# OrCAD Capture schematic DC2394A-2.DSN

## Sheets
1 PAGE1: size Custom
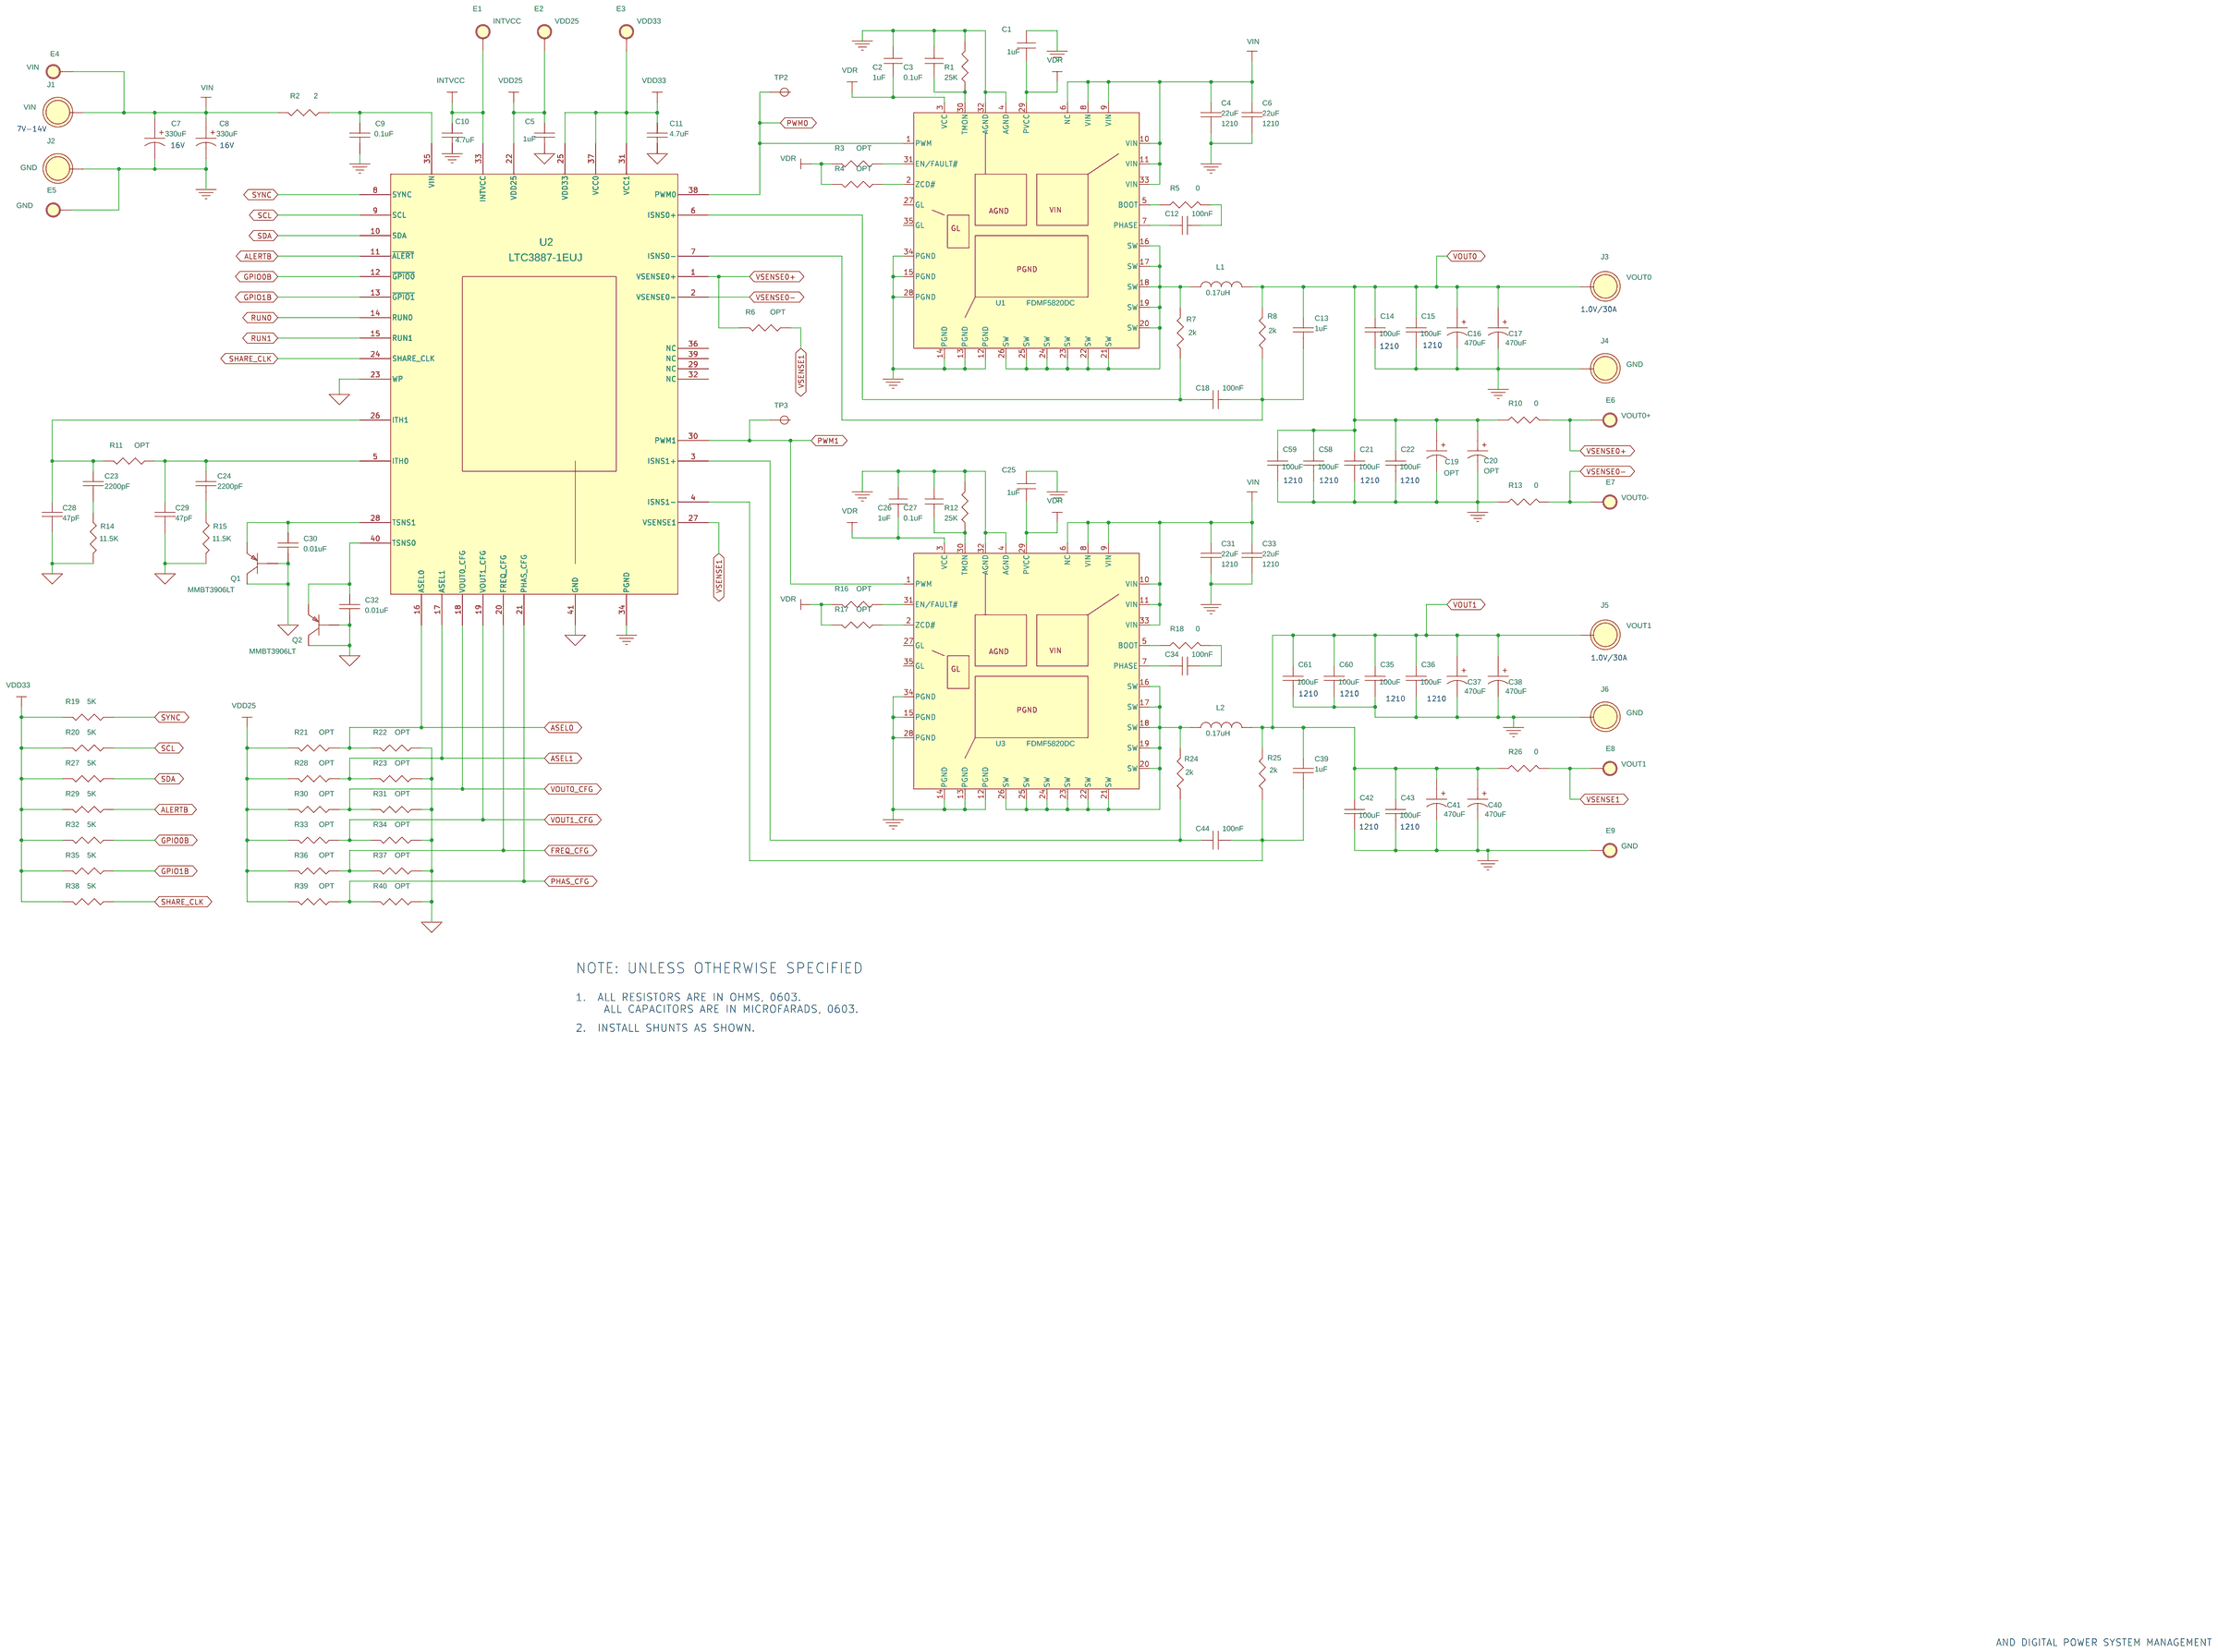
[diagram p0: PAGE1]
2 PAGE2: size Custom; title: HIGH DENSITY  DC/DC CONVERTER WITH POWER SYSTEM MANAGEMENT; rev: 1; company: TM
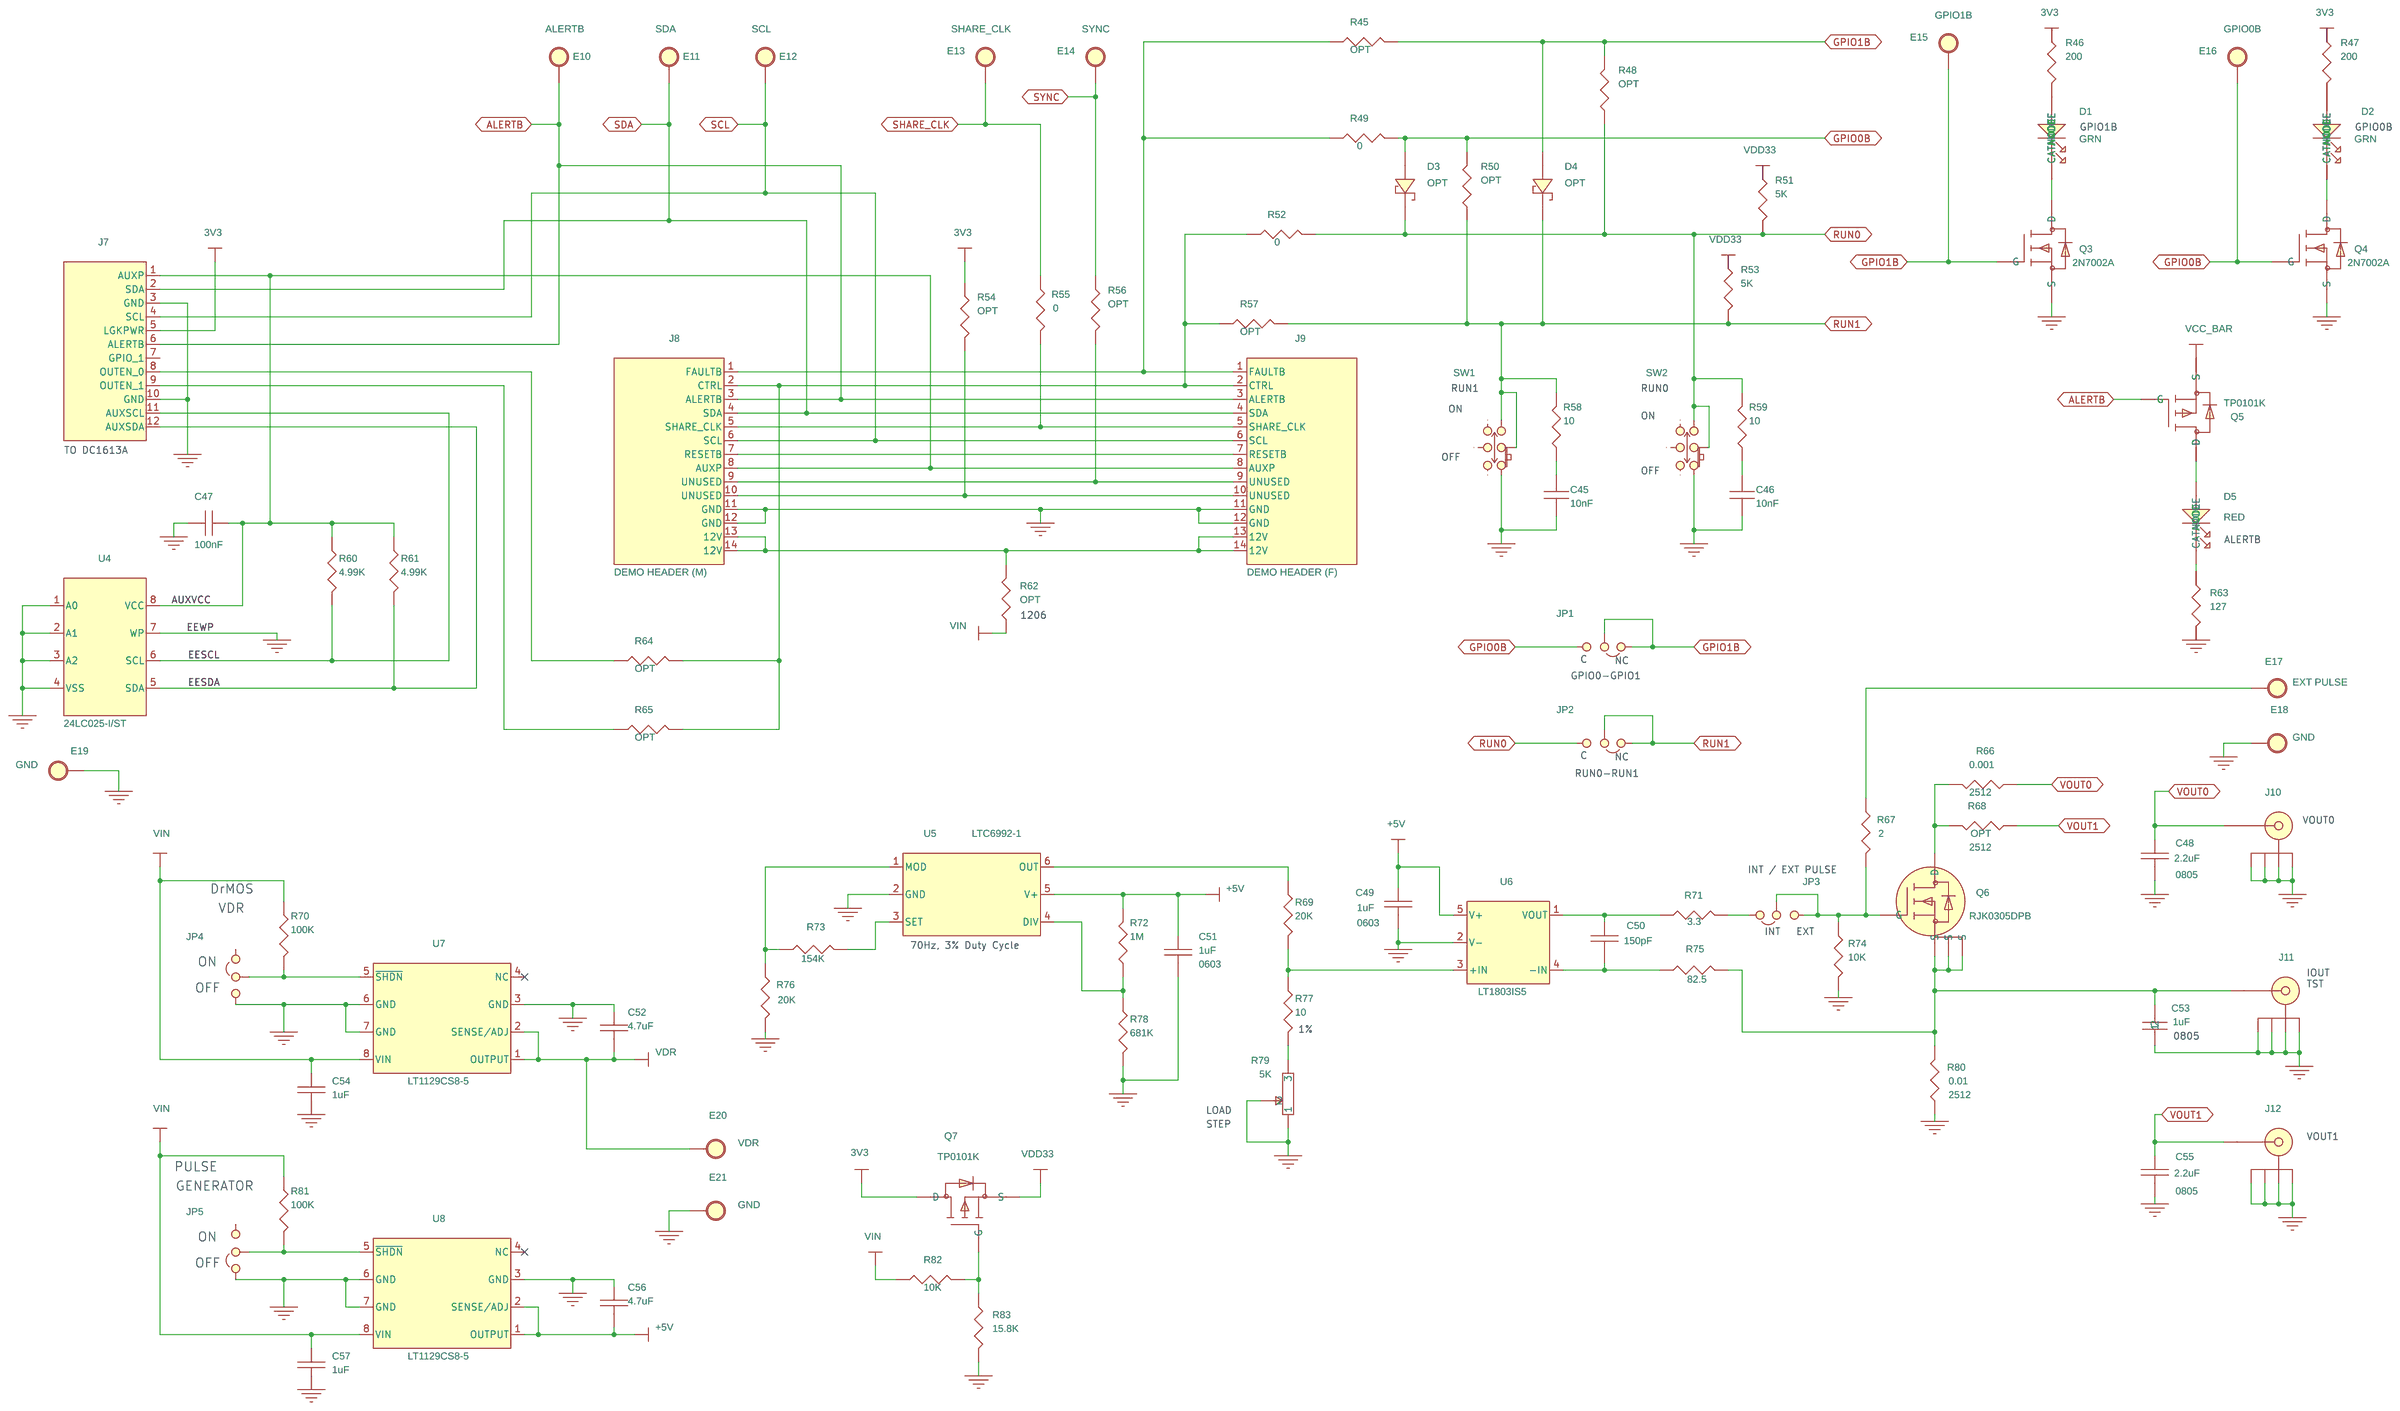
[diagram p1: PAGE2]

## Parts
sheet PAGE1
C1  1uF  [0402]
C2  1uF  [0402]
C3  0.1uF  [0402]
C4  22uF  [1210]
C5  1uF  [0603]
C6  22uF  [1210]
C7  330uF  [CAP_SANYO_F12]
C8  330uF  [CAP_SANYO_F12]
C9  0.1uF  [0603]
C10  4.7uF  [0603]
C11  4.7uF  [0603]
C12  100nF  [0402]
C13  1uF  [0603]
C14  100uF  [1210]
C15  100uF  [1210]
C16  470uF  [SANYO-C3-D2E(TPE)]
C17  470uF  [SANYO-C3-D2E(TPE)]
C18  100nF  [0603]
C19  OPT  [SANYO-C3-D2E(TPE)]
C20  OPT  [SANYO-C3-D2E(TPE)]
C21  100uF  [1210]
C22  100uF  [1210]
C23  2200pF  [0603]
C24  2200pF  [0603]
C25  1uF  [0402]
C26  1uF  [0402]
C27  0.1uF  [0402]
C28  47pF  [0603]
C29  47pF  [0603]
C30  0.01uF  [0603]
C31  22uF  [1210]
C32  0.01uF  [0603]
C33  22uF  [1210]
C34  100nF  [0402]
C35  100uF  [1210]
C36  100uF  [1210]
C37  470uF  [SANYO-C3-D2E(TPE)]
C38  470uF  [SANYO-C3-D2E(TPE)]
C39  1uF  [0603]
C40  470uF  [SANYO-C3-D2E(TPE)]
C41  470uF  [SANYO-C3-D2E(TPE)]
C42  100uF  [1210]
C43  100uF  [1210]
C44  100nF  [0603]
C58  100uF  [1210]
C59  100uF  [1210]
C60  100uF  [1210]
C61  100uF  [1210]
E1  TURRETS  [TURRETS]
E2  TURRETS  [TURRETS]
E3  TURRETS  [TURRETS]
E4  TURRETS  [TURRETS]
E5  GND  [TURRETS]
E6  TURRETS  [TURRETS]
E7  TURRETS  [TURRETS]
E8  TURRETS  [TURRETS]
E9  TURRETS  [TURRETS]
J1  VIN  [KEY-575-4]
J2  GND  [KEY-575-4]
J3  VOUT0  [CON\LUG\10]
J4  GND  [CON\LUG\10]
J5  VOUT1  [CON\LUG\10]
J6  GND  [CON\LUG\10]
L1  0.17uH  [PA0515]
L2  0.17uH  [PA0515]
Q1  MMBT3906LT  [SOT-416]
Q2  MMBT3906LT  [SOT-416]
R1  25K  [0402]
R2  2  [0603]
R3  OPT  [0402]
R4  OPT  [0402]
R5  0  [0402]
R6  OPT  [0603]
R7  2k  [0603]
R8  2k  [0603]
R10  0  [0603]
R11  OPT  [0603]
R12  25K  [0402]
R13  0  [0603]
R14  11.5K  [0603]
R15  11.5K  [0603]
R16  OPT  [0402]
R17  OPT  [0402]
R18  0  [0402]
R19  5K  [0603]
R20  5K  [0603]
R21  OPT  [0603]
R22  OPT  [0603]
R23  OPT  [0603]
R24  2k  [0603]
R25  2k  [0603]
R26  0  [0603]
R27  5K  [0603]
R28  OPT  [0603]
R29  5K  [0603]
R30  OPT  [0603]
R31  OPT  [0603]
R32  5K  [0603]
R33  OPT  [0603]
R34  OPT  [0603]
R35  5K  [0603]
R36  OPT  [0603]
R37  OPT  [0603]
R38  5K  [0603]
R39  OPT  [0603]
R40  OPT  [0603]
TP2  TURRETS  [PAD]
TP3  TURRETS  [PAD]
U1  DC/DC Converters  [FDMF5821DC]
U2  LTC3887-1EUJ  [UJ-40-QFN(6X6mm)]
U3  DC/DC Converters  [FDMF5821DC]
sheet PAGE2
C45  10nF  [0603]
C46  10nF  [0603]
C47  100nF  [0603]
C48  2.2uF  [0805]
C49  1uF  [0603]
C50  150pF  [0603]
C51  1uF  [0603]
C52  4.7uF  [1206]
C53  1uF  [0805]
C54  1uF  [1206]
C55  2.2uF  [0805]
C56  4.7uF  [0603]
C57  1uF  [1206]
D1  LED  [WURTH_LED]
D2  LED  [WURTH_LED]
D3  OPT  [SOD323]
D4  OPT  [SOD323]
D5  LED  [WURTH_LED]
E10  TURRETS  [TURRETS]
E11  TURRETS  [TURRETS]
E12  TURRETS  [TURRETS]
E13  TURRETS  [TURRETS]
E14  TURRETS  [TURRETS]
E15  TURRETS  [TURRETS]
E16  TURRETS  [TURRETS]
E17  TURRETS  [TURRETS]
E18  TURRETS  [TURRETS]
E19  TURRETS  [TURRETS]
E20  TURRETS  [TURRETS]
E21  TURRETS  [TURRETS]
J7  HD2X6-079  [HD2X6-079-MOLEX]
J8  DEMO HEADER (M)  [NPPN072FJFN]
J9  DEMO HEADER (F)  [NPPN072FJFN-RC]
J10  CONNEX 112404  [BNC]
J11  CONNEX 112404  [BNC]
J12  CONNEX 112404  [BNC]
JP1  JP3X1/079\NO\12  [HD1X3-079]
JP2  JP3X1/079\NO\12  [HD1X3-079]
JP3  JP3X1/079\NO\12  [HD1X3-079]
JP4  JP3X1/079\NO\12  [HD1X3-079]
JP5  JP3X1/079\NO\12  [HD1X3-079]
Q3  2N7002A  [SOT-23]
Q4  2N7002A  [SOT-23]
Q5  TP0101K  [SOT-23]
Q6  RJK0305DPB  [LFPAK]
Q7  TP0101K  [SOT-23]
R45  OPT  [0603]
R46  200  [0603]
R47  200  [0603]
R48  OPT  [0603]
R49  0  [0603]
R50  OPT  [0603]
R51  5K  [0603]
R52  0  [0603]
R53  5K  [0603]
R54  OPT  [0603]
R55  0  [0603]
R56  OPT  [0603]
R57  OPT  [0603]
R58  10  [0603]
R59  10  [0603]
R60  4.99K  [0603]
R61  4.99K  [0603]
R62  OPT  [0603]
R63  127  [0603]
R64  OPT  [0603]
R65  OPT  [0603]
R66  0.001  [2512]
R67  2  [0603]
R68  OPT  [2512]
R69  20K  [0603]
R70  100K  [0603]
R71  3.3  [0603]
R72  1M  [0603]
R73  154K  [0603]
R74  10K  [0603]
R75  82.5  [0603]
R76  20K  [0603]
R77  10  [0603]
R78  681K  [0603]
R79  5K  [POTENTIOMETER/3386]
R80  0.01  [2512]
R81  100K  [0603]
R82  10K  [0603]
R83  15.8K  [0603]
SW1  JP3X1/079\NO\12  [JS202011]
SW2  JP3X1/079\NO\12  [JS202011]
U4  24LC025-I/ST  [TSSOP-8_4.4MM]
U5  LTC6992-1  [S6-TSOT23]
U6  LT1803IS5  [S5-TSOT23]
U7  LT1129CS8-5  [SO8NB]
U8  LT1129CS8-5  [SO8NB]

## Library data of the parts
C1 C25 = CAP-NP: CAP, 0603 2.2uF 10% 16V X5R; Grade: X5R; Voltage rating: 16V
C2 C3 C26 C27 = CAP-NP: CAP, 0603 2.2uF 10% 16V X5R; Grade: X5R; Part Number: C0603C225K4PAC; Voltage rating: 16V
C4 C6 C31 C33 = CAP1210_2: Component: cap; Manufacturer: Taiyo Yuden; Manufacturer P/N: GMK325BJ106KN-T; Tolerance: 10%; Type: cer 1210; Vendor: Digikey; Vendor P/N: 587-1439-1-ND; Volts/Amps/Watts: 35V
C5 C10 = CAP_3: CAP, 0402 1uF 20% 10V X5R; Manufacturer: Taiyo Yuden; Manufacturer P/N: EMK107B7105KA-T; Part Number: TDK C1005X5R1A105M; Type: cer 0603 X7R; Vendor: Digikey; Vendor P/N: 587-1241-1-ND; Volts/Amps/Watts: 10V
C7 C8 = CAPR12X5_0: Component: cap; Manufacturer: SANYO; Manufacturer P/N: 16SVP330M; Tolerance: 20%; Type: OS-CON; Volts/Amps/Watts: 16V
C9 = CAP_3: CAP, 0402 0.1uF 10% 16V X7R; Manufacturer: TDK; Manufacturer P/N: C1608X7R1H104K; Part Number: AVX 0402YC103KAT2A; Part Type: 0402; Tolerance: 10%; Type: cer 0603 X7R; Vendor: Digikey; Vendor P/N: 445-1314-1-ND; Volts/Amps/Watts: 16V
C11 = CAP_3: CAP, 0402 1uF 20% 10V X5R; Manufacturer: Taiyo Yuden; Manufacturer P/N: EMK107B7105KA-T; Part Number: TDK C1005X5R1A105M; Part Type: 0402; Type: cer 0603 X7R; Vendor: Digikey; Vendor P/N: 587-1241-1-ND; Volts/Amps/Watts: 10V
C12 C18 C34 C44 = EMK107BJ224MA: CAP, 0603 0.22uF 10% 25V X5R
C13 C39 = CAP_3: CAP, 0805 47uF 20% 6.3V X5R; Component: cap; Manufacturer: TDK; Manufacturer P/N: C3225X5R0J107M; Part Number: TAIYO YUDEN JMK212BJ476MG-T; Part Type: CAP1210; Tolerance: 20%; Type: cer 1210 X5R; Vendor: Digikey; Vendor P/N: 445-1437-1-ND; Volts/Amps/Watts: 6.3v
C14 C15 C21 C22 C58-C61 = CAP_3: Component: cap; Manufacturer: TDK; Manufacturer P/N: C3225X5R0J107M; Part Type: CAP1210; Tolerance: 20%; Type: cer 1210 X5R; Vendor: Digikey; Vendor P/N: 445-1437-1-ND; Volts/Amps/Watts: 6.3v
C16 C17 C19 C20 C37 C38 C40 C41 = CAPR12X5_0: Component: cap; Manufacturer: SANYO; Manufacturer P/N: 6TPF330M9L; Tolerance: 20%; Type: TANT; Volts/Amps/Watts: 6.3V
C23 C24 = CAP_3: CAP, 0402 1000pF 10% 25V X7R; Component: cap; Manufacturer: TDK; Manufacturer P/N: C1608C0G1H102J; Part Number: AVX 04023C102KAT2A; Tolerance: 5%; Type: cer 0603; Vendor: Digikey; Vendor P/N: 445-1293-1-ND; Volts/Amps/Watts: 50V
C28 C29 = CAP_3: CAP, 0402 47pF 10% 50V NPO; Component: cap; Manufacturer: TDK; Manufacturer P/N: C1608C0G1H101J; Part Number: AVX 04025A470KAT; Tolerance: 5%; Type: cer 0603; Vendor: Digikey; Vendor P/N: 445-1281-1-ND
C30 C32 = CAP0603_1: CAP, 0402 0.1uF 10% 16V X7R; Component: cap; Manufacturer: TDK; Manufacturer P/N: C1608X7R1H103K; Part Number: AVX 0402YC103KAT2A; Part Type: 0402; Tolerance: 10%; Type: cer 0603; Vendor: Digikey; Vendor P/N: 445-1311-1-ND; Volts/Amps/Watts: 50V
C35 C36 C42 C43 = CAP_3: Component: cap; Manufacturer: TDK; Manufacturer P/N: C3225X5R0J107M; Tolerance: 20%; Type: cer 1210 X5R; Vendor: Digikey; Vendor P/N: 445-1437-1-ND; Volts/Amps/Watts: 6.3v
E1 = TURRETS_2: Label: INTVCC; Vendor: Digikey; Vendor P/N: 1593-2K-ND
E2 = TURRETS_2: Label: VDD25; Vendor: Digikey; Vendor P/N: 1593-2K-ND
E3 = TURRETS_2: Label: VDD33; Vendor: Digikey; Vendor P/N: 1593-2K-ND
E4 = TURRETS_2: Label: VIN; Manufacturer: Keystone; Manufacturer P/N: 1593-2; Vendor: Digikey; Vendor P/N: 1593-2K-ND
E5 = TURRETS_2: Manufacturer: Keystone; Manufacturer P/N: 1593-2; Vendor: Digikey; Vendor P/N: 1593-2K-ND
E6 = TURRETS_2: Label: VOUT0+; Vendor: Digikey; Vendor P/N: 1593-2K-ND
E7 = TURRETS_2: Label: VOUT0-; Vendor: Digikey; Vendor P/N: 1593-2K-ND
E8 = TURRETS_2: Label: VOUT1; Vendor: Digikey; Vendor P/N: 1593-2K-ND
E9 = TURRETS_2: Label: GND; Vendor: Digikey; Vendor P/N: 1593-2K-ND
J1 = E_4: STATUS: 1.6V, 1.8V, 2.0V OR 2.5V @ 15A
J2 J4 J6 = E_4: STATUS: 1.6V, 1.8V, 2.0V OR 2.5V @ 15A; VALUE2: J1
J3 J5 = E_4: VALUE2: 1V@80A
L1 L2 = 744355147_Wurth: 4th Part Field: WURTH EL.; 5th Part Field: DELTA
Q1 Q2 = MMBT3906LT1_0: XSTR, PNP SMALL SIGNAL; Component: trans; Manufacturer P/N: MMBT3906LT1G; Part Number: ON SEMI MMBT3906TTI; Part Type: MMBT3906LT1; Vendor P/N: MMBT3906LT1GOSCT-ND
R1 R12 = CJ06-000M: RES, 0603 0 OHM JUMPER
R2 = RES0603_9: RES, 0402 2 OHMS 1% 1/16W; Manufacturer: Panasonic; Part Number: VISHAY CRCW04022R00FNEA; Part Type: 0402; Vendor: Digikey; Vendor P/N: P100HCT-ND; Volts/Amps/Watts: 0.1W
R3 R4 R16 R17 = RES0603_9: Manufacturer: Panasonic; Manufacturer P/N: ERJ-3EKF2002V; Vendor: Digikey; Vendor P/N: P20.0KHCT-ND; Volts/Amps/Watts: 0.1W
R5 R7 R8 R10 R13 R18 R24-R26 = CJ06-000M: RES, 0603 0 OHM JUMPER; Part Number: YAGEO RC0603FR-070RL
R6 R11 = RES0603_9: RES, 0402 0 OHM JUMPER; Manufacturer: Panasonic; Manufacturer P/N: ERJ-3EKF2002V; Part Number: VISHAY CRCW04020000Z0EA; Vendor: Digikey; Vendor P/N: P20.0KHCT-ND; Volts/Amps/Watts: 0.1W
R14 R15 = RES0603_9: RES, 0402 4.53k OHMS 1% 1/16W; Component: res; Label: <label>; Manufacturer: Panasonic; Manufacturer P/N: ERJ-3EKF5901V; Part Number: VISHAY CRCW04024K53FKED; Tolerance: 1%; Vendor: Digikey; Vendor P/N: P5.90KHCT-ND; Volts/Amps/Watts: 0.1W
R19 R20 R27 R29 R32 R35 R38 = RES0603_9: RES, 0402 5k OHMS 5% 1/16W; Manufacturer: Panasonic; Manufacturer P/N: ERJ-3EKF2002V; Part Number: VISHAY CRCW04025K00JNED; Vendor: Digikey; Vendor P/N: P20.0KHCT-ND; Volts/Amps/Watts: 0.1W
R21-R23 R28 R30 R31 R33 R34 R36 R37 R39 R40 = RES0603_9: RES, 0603 OPTION; Manufacturer: Panasonic; Manufacturer P/N: ERJ-3EKF2002V; Part Number: OPTION; Vendor: Digikey; Vendor P/N: P20.0KHCT-ND; Volts/Amps/Watts: 0.1W
TP2 TP3 = PAD_2: Component: tp; Label: <Label>; Vendor: Digikey; Vendor P/N: 1593-2K-ND
U1 U3 = R2J20602NP(Renesas)_5: 5th Part Field: FDMF5820DC
U2 = LTC3880-M0001_15: IC,; Component: IC; Manufacturer: LTC; Manufacturer P/N: LTC3880_M0001; Part Number: LINEAR TECH LTC3880EUJ; Part Type: LTC3880EUF; Vendor: LTC; Vendor P/N: LTC3880_M0001
C45 C46 = CAP_NP: CAP, 0603 10nF 10% 25V X7R; Part Number: AVX 06033C103KAT2A
C47 = CAP_NP: CAP, 0603 100nF 20% 16V X7R; Part Number: AVX 0603YC104MAT2A
C48 C55 = CAP1206_1: Manufacturer: Kemet; Manufacturer P/N: C1206C106K8RACTU; Tolerance: 10%; Type: cer 1206 X7R; Vendor: Digikey; Vendor P/N: 399-4937-1-ND; Volts/Amps/Watts: 10V
C49 C51 C54 C57 = CAP1206_1: Manufacturer: AVX; Manufacturer P/N: 12063C105KAT2A; Tolerance: 10%; Type: cer 1206 X7R; Vendor: Digikey; Vendor P/N: 478-1567-1-ND; Volts/Amps/Watts: 25V
C50 = CAP0603_2: Component: cap; Manufacturer: TDK; Manufacturer P/N: C1608C0G1H102J; Tolerance: 5%; Type: cer 0603; Vendor: Digikey
C52 C56 = CAP1206_1: Manufacturer: AVX; Tolerance: 10%; Type: cer 1206 X7R; Vendor: Digikey; Vendor P/N: 478-1567-1-ND; Volts/Amps/Watts: 25V
C53 = CAP_NP_1: CAP, 0603 1.5nF 10% 50V X7R; Part Number: AVX 06033C152KAT
D1 D2 = LED_1: 1%: GRN
D3 D4 = DIODE_SCHOTTKY_9: DIODE, SCHOTTKY 30V, 100mA; Part Number: CENTRAL SEMI CMDSH-3-TR
D5 = LED_1: 1%: RED
E10 = TURRETS_2: Label: ALERTB; Manufacturer: Keystone; Manufacturer P/N: 1593-2; Vendor: Digikey; Vendor P/N: 1593-2K-ND
E11 = TURRETS_2: Label: SDA; Manufacturer: Keystone; Manufacturer P/N: 1593-2; Vendor: Digikey; Vendor P/N: 1593-2K-ND
E12 = TURRETS_2: Label: SCL; Manufacturer: Keystone; Manufacturer P/N: 1593-2; Vendor: Digikey; Vendor P/N: 1593-2K-ND
E13 = TURRETS_2: Label: SHARE_CLK; Manufacturer: Keystone; Manufacturer P/N: 1593-2; Vendor: Digikey; Vendor P/N: 1593-2K-ND
E14 = TURRETS_2: Label: SYNC; Manufacturer: Keystone; Manufacturer P/N: 1593-2; Vendor: Digikey; Vendor P/N: 1593-2K-ND
E15 = TURRETS_2: Label: GPIO1B; Manufacturer: Keystone; Manufacturer P/N: 1593-2; Vendor: Digikey; Vendor P/N: 1593-2K-ND
E16 = TURRETS_2: Label: GPIO0B; Manufacturer: Keystone; Manufacturer P/N: 1593-2; Vendor: Digikey; Vendor P/N: 1593-2K-ND
E17 = TURRETS_2: Label: EXT PULSE; Manufacturer: Keystone; Manufacturer P/N: 1593-2; Vendor: Digikey; Vendor P/N: 1593-2K-ND
E18 E19 E21 = TURRETS_2: Label: GND; Manufacturer: Keystone; Manufacturer P/N: 1593-2; Vendor: Digikey; Vendor P/N: 1593-2K-ND
E20 = TURRETS_2: Label: VDR; Manufacturer: Keystone; Manufacturer P/N: 1593-2; Vendor: Digikey; Vendor P/N: 1593-2K-ND
J7 = HD2X6-079-PMBUS_2: HEADER, 12PIN 2mm STR DL; Label: DC1427A HEADER; Manufacturer: MOLEX; Manufacturer P/N: 87831-1220; Part Number: FCI 98414-G06-12ULF; Type: header 12POS 2MM VERT; Vendor: Digikey; Vendor P/N: WM18561-ND
J8 = PMBUS_HEADER20_3: HEADER, 20PIN DUAL ROW R/A; Component: con; Manufacturer: Mill Max; Manufacturer P/N: 802-40-020-20-0001; Part Number: MILL MAX 802-40-020-20-0001; Part Type: HDR_2X10_RA_REV; Type: header RA 20 dual row; Vendor: LTC; Vendor P/N: 802-40-020-20-001
J9 = PMBUS_CONNECTOR20_3: CONN, SOCKET 20PIN  DUAL ROW R/A; Component: con; Manufacturer: Mill Max; Manufacturer P/N: 803-93-020-20-001; Part Number: MILL MAX 803-93-020-20-001; Part Type: HDR2X10RA; Type: conn  RA 20 dual row; Vendor: LTC; Vendor P/N: 803-93-020-20-001
J10-J12 = BNC5-SCH_0: CONN,BNC,5 PINS
JP1-JP3 JP5 = JP3X1_079_NO_12_2
JP4 = JP3X1_079_NO_12_1
Q3 Q4 = TRANSISTOR_0: XSTR, N-CHANNEL DMOS FET
Q5 Q7 = P-MOSFET: XSTR, N-CHANNEL DMOS FET
Q6 = MOS_FET_5: XSTR, N-CHANNEL DMOS FET
R45 R49 R52 R57 = RES0603_0: RES, 0603 0 OHMS JUMPER; Label: OPT 0; Manufacturer: Rohm; Manufacturer P/N: RHM0.0GCT-ND; Part Number: VISHAY CRCW06030000Z0EA; Tolerance: 5%; Vendor: Digikey; Vendor P/N: RHM0.0GCT-ND; Volts/Amps/Watts: 0.1W
R46 R47 R63 = RES0603_9: Label: OPT 0; Manufacturer: Rohm; Manufacturer P/N: RHM0.0GCT-ND; Tolerance: 5%; Vendor: Digikey; Vendor P/N: RHM0.0GCT-ND; Volts/Amps/Watts: 0.1W
R48 R50 R51 R53 R54 R56 R65 = RES0603_0: RES, 0603 OPTION; Label: OPT 0; Manufacturer: Rohm; Manufacturer P/N: RHM0.0GCT-ND; Part Number: OPTION; Tolerance: 5%; Vendor: Digikey; Vendor P/N: RHM0.0GCT-ND; Volts/Amps/Watts: 0.1W
R55 = RES0603_0: RES, 0603 0 OHMS JUMPER; Manufacturer: Rohm; Manufacturer P/N: RHM0.0GCT-ND; Part Number: VISHAY CRCW06030000Z0EA; Tolerance: 5%; Vendor: Digikey; Vendor P/N: RHM0.0GCT-ND; Volts/Amps/Watts: 0.1W
R58 R59 = RES0603_1: RES, 0603 10 OHMS 5% 1/10W; Manufacturer: Rohm; Manufacturer P/N: RHM0.0GCT-ND; Part Number: VISHAY CRCW060310R0JNEA; Tolerance: 5%; Vendor: Digikey; Vendor P/N: RHM0.0GCT-ND; Volts/Amps/Watts: 0.1W
R60 R61 = RES0603_0: RES, 0603 4.99K OHMS 1% 1/10W; Manufacturer: ROHM; Manufacturer P/N: MCR03EZPFX4991; Part Number: VISHAY CRCW06034K99FKEA; Vendor: Digikey; Vendor P/N: RHM4.99KHCT-ND; Volts/Amps/Watts: 0.1w
R62 R64 = RES0603_3: RES, 0603 OPTION; Label: OPT 0; Manufacturer: Rohm; Manufacturer P/N: RHM0.0GCT-ND; Part Number: OPTION; Tolerance: 5%; Vendor: Digikey; Vendor P/N: RHM0.0GCT-ND; Volts/Amps/Watts: 0.1W
R66 R68 R80 = RES0603_5: Label: 1W; Manufacturer: VISHAY; Manufacturer P/N: CRCW251230R0JNEG; Tolerance: 5%; Vendor: Digikey; Vendor P/N: 541-30XCT-ND; Volts/Amps/Watts: 0.1W
R67 R69 R71-R78 = RES0603_9: Manufacturer: ROHM; Manufacturer P/N: MCR03EZPFX4991; Vendor: Digikey; Vendor P/N: RHM4.99KHCT-ND; Volts/Amps/Watts: 0.1w
R70 R81 = RES0603_11
R79 = POT_A_0
R82 = RES0603_9: Manufacturer: ROHM; Manufacturer P/N: MCR03EZPFX1002; Vendor: Digikey; Vendor P/N: RHM10.0KHCT-ND; Volts/Amps/Watts: 0.1W
R83 = RES0603_9
SW1 SW2 = JP3X1_079_NO_12_3: SWITCH, SUBMINATURE SLIDE; Part Number: C&K JS202011CQN
U4 = 24LC025-I_SN: IC, 24LC05-I/ST; Part Number: MICROCHIP 24LC025-I/ST
U5 = LT1129CS8-3_0.3
U6 = LT1129CS8-3_3.3
U7 U8 = LT1129CS8-3.3

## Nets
3V3: J7.5(LGKPWR) Q5.2(S) Q7.3(D) R46.1 R47.1 R54.1
+5V: C49.1 C51.1 C56.2 R72.2 U5.5(V+) U6.5(V+) U8.1(OUTPUT) U8.2(SENSE/ADJ)
GND_POWER: C1.1 C2.1 C3.1 C4.2 C6.2 C7.2 C8.2 C9.2 C10.2 C14.2 C15.2 C16.2 C17.2 C19.2 C20.2 C21.2 C22.2 C25.1 C26.1 C27.1 C31.2 C33.2 C35.2 C36.2 C37.2 C38.2 C40.2 C41.2 C42.2 C43.2 C45.2 C46.2 C47.2 C48.2 C49.2 C51.2 C52.1 C53.1 C54.2 C55.2 C56.1 C57.2 C58.2 C59.2 C60.2 C61.2 E5.1(TP) E9.1(TP) E18.1(TP) E19.1(TP) E21.1(TP) J2.1(A) J4.1(A) J6.1(A) J7.3(GND) J7.10(GND) J8.11(GND) J8.12(GND) J9.11(GND) J9.12(GND) J10.2 J10.3 J10.4 J10.5 J11.2 J11.3 J11.4 J11.5 J12.2 J12.3 J12.4 J12.5 JP4.1 JP5.1 Q3.2(S) Q4.2(S) R1.1 R12.1 R13.2 R63.2 R74.2 R76.2 R78.2 R79.1 R79.2 R80.1 R83.2 SW1.3 SW2.3 U1.4(AGND) U1.12(PGND) U1.13(PGND) U1.14(PGND) U1.15(PGND) U1.28(PGND) U1.32(AGND) U1.34(PGND) U2.34(PGND) U3.4(AGND) U3.12(PGND) U3.13(PGND) U3.14(PGND) U3.15(PGND) U3.28(PGND) U3.32(AGND) U3.34(PGND) U4.1(A0) U4.2(A1) U4.3(A2) U4.4(VSS) U4.7(WP) U5.2(GND) U6.2(V-) U7.3(GND) U7.6(GND) U7.7(GND) U8.3(GND) U8.6(GND) U8.7(GND)
GND_SIGNAL: C5.2 C11.2 C28.2 C29.2 C30.2 C32.2 Q1.1(BASE) Q1.3(COLLECTOR) Q2.1(BASE) Q2.3(COLLECTOR) R14.2 R15.2 R22.1 R23.1 R31.1 R34.1 R37.1 R40.1 U2.23(WP) U2.41(GND)
VDD25: C5.1 E2.1(TP) R21.2 R28.2 R30.2 R33.2 R36.2 R39.2 U2.22(VDD25)
VDD33: C11.1 E3.1(TP) Q7.2(S) R19.2 R20.2 R27.2 R29.2 R32.2 R35.2 R38.2 R51.1 R53.1 U2.25(VDD33) U2.31(VCC1) U2.37(VCC0)
VIN: C4.1 C6.1 C7.1 C8.1 C31.1 C33.1 C54.1 C57.1 E4.1(TP) J1.1(A) R2.1 R62.1 R70.1 R81.1 R82.1 U1.6(NC) U1.8(VIN) U1.9(VIN) U1.10(VIN) U1.11(VIN) U1.33(VIN) U3.6(NC) U3.8(VIN) U3.9(VIN) U3.10(VIN) U3.11(VIN) U3.33(VIN) U7.8(VIN) U8.8(VIN)
ALERTB: E10.1(TP) J7.6(ALERTB) J8.3(ALERTB) J9.3(ALERTB) Q5.1(G) R29.1 U2.11(~{ALERT})
ASEL0: R21.1 R22.2 U2.16(ASEL0)
ASEL1: R23.2 R28.1 U2.17(ASEL1)
AUXVCC: C47.1 J7.1(AUXP) J8.8(AUXP) J9.8(AUXP) R60.1 R61.1 U4.8(VCC)
EESCL: J7.11(AUXSCL) R60.2 U4.6(SCL)
EESDA: J7.12(AUXSDA) R61.2 U4.5(SDA)
FREQ_CFG: R36.1 R37.2 U2.20(FREQ_CFG)
GPIO0B: D3.2(ANODE) E16.1(TP) JP1.3 Q4.1(G) R32.1 R49.2 R50.2 U2.12(~{GPIO0})
GPIO1B: D4.2(ANODE) E15.1(TP) JP1.1 JP1.2 Q3.1(G) R35.1 R45.2 R48.2 U2.13(~{GPIO1})
INTVCC: C10.1 E1.1(TP) U2.33(INTVCC)
PHAS_CFG: R39.1 R40.2 U2.21(PHAS_CFG)
PWM0: TP2.1(TP) U1.1(PWM) U2.38(PWM0)
PWM1: TP3.1(TP) U2.30(PWM1) U3.1(PWM)
RUN0: D3.1(CATHODE) JP2.3 R48.1 R51.2 R52.2 R59.2 SW2.1 SW2.2 U2.14(RUN0)
RUN1: D4.1(CATHODE) JP2.1 JP2.2 R50.1 R53.2 R57.2 R58.2 SW1.1 SW1.2 U2.15(RUN1)
SCL: E12.1(TP) J7.4(SCL) J8.6(SCL) J9.6(SCL) R20.1 U2.9(SCL)
SDA: E11.1(TP) J7.2(SDA) J8.4(SDA) J9.4(SDA) R27.1 U2.10(SDA)
SHARE_CLK: E13.1(TP) R38.1 R55.1 U2.24(SHARE_CLK)
SYNC: E14.1(TP) R19.1 R56.1 U2.8(SYNC)
VDR: C1.2 C2.2 C25.2 C26.2 C52.2 E20.1(TP) R3.2 R4.2 R16.2 R17.2 U1.3(VCC) U1.29(PVCC) U3.3(VCC) U3.29(PVCC) U7.1(OUTPUT) U7.2(SENSE/ADJ)
VOUT0: C13.1 C14.1 C15.1 C16.1 C17.1 C19.1 C20.1 C21.1 C22.1 C48.1 C58.1 C59.1 J3.1(A) J10.1 L1.2 R8.1 R10.2 R66.1
VOUT0_CFG: R30.1 R31.2 U2.18(VOUT0_CFG)
VOUT1: C35.1 C36.1 C37.1 C38.1 C39.1 C40.1 C41.1 C42.1 C43.1 C55.1 C60.1 C61.1 J5.1(A) J12.1 L2.2 R25.1 R26.2 R68.1
VOUT1_CFG: R33.1 R34.2 U2.19(VOUT1_CFG)
VSENSE0+: E6.1(TP) R6.2 R10.1 U2.1(VSENSE0+)
VSENSE0-: E7.1(TP) R13.1 U2.2(VSENSE0-)
VSENSE1: E8.1(TP) R6.1 R26.1 U2.27(VSENSE1)
N25214003: L1.1 R7.1 U1.16(SW) U1.17(SW) U1.18(SW) U1.19(SW) U1.20(SW) U1.21(SW) U1.22(SW) U1.23(SW) U1.24(SW) U1.25(SW) U1.26(SW)
N25214009: C44.1 R24.2 U2.3(ISNS1+)
N25214017: C39.2 C44.2 R25.2 U2.4(ISNS1-)
N25214035: C18.1 R7.2 U2.6(ISNS0+)
N25214110: R3.1 U1.31(EN/FAULT#)
N25214136: R4.1 U1.2(ZCD#)
N25214154: C12.2 R5.1
N25214160: R5.2 U1.5(BOOT)
N25214170: C12.1 U1.7(PHASE)
N25214212: L2.1 R24.1 U3.16(SW) U3.17(SW) U3.18(SW) U3.19(SW) U3.20(SW) U3.21(SW) U3.22(SW) U3.23(SW) U3.24(SW) U3.25(SW) U3.26(SW)
N25214264: R16.1 U3.31(EN/FAULT#)
N25214329: R17.1 U3.2(ZCD#)
N25214339: C34.2 R18.1
N25214345: R18.2 U3.5(BOOT)
N25214355: C34.1 U3.7(PHASE)
N25214395: C27.2 R12.2 U3.30(TMON)
N25214489: C3.2 R1.2 U1.30(TMON)
N25214670: C13.2 C18.2 R8.2 U2.7(ISNS0-)
N25271339: C9.1 R2.2 U2.35(VIN)
N25275077: C24.1 C29.1 R11.1 U2.5(ITH0)
N25275079: C24.2 R15.1
N25275098: C23.1 C28.1 R11.2 U2.26(ITH1)
N25275100: C23.2 R14.1
N25276080: C32.1 Q2.2(EMITTER) U2.40(TSNS0)
N25276115: C30.1 Q1.2(EMITTER) U2.28(TSNS1)
N25447560: J8.2(CTRL) J9.2(CTRL) R52.1 R57.1 R64.2 R65.2
N25447562: J8.10(UNUSED) J9.10(UNUSED) R54.2
N25447566: J8.1(FAULTB) J9.1(FAULTB) R45.1 R49.1
N25447592: R73.2 U5.3(SET)
N25447600: JP3.1 R71.2
N25447602: JP3.2 JP3.3 Q6.4(G) R67.2 R74.1
N25447616: R73.1 R76.1 U5.1(MOD)
N25447637: R69.1 U5.6(OUT)
N25447647: R72.1 R78.1 U5.4(DIV)
N25447700: C53.2 J11.1 Q6.1(S) Q6.2(S) Q6.3(S) R75.2 R80.2
N25447880: C50.2 R75.1 U6.4(-IN)
N25447884: R77.2 R79.3
N25447900: C50.1 R71.1 U6.1(VOUT)
N25447906: R69.2 R77.1 U6.3(+IN)
N25447976: Q6.5(D) R66.2 R68.2
N25447980: E17.1(TP) R67.1
N25448498: J8.5(SHARE_CLK) J9.5(SHARE_CLK) R55.2
N25448502: J8.7(RESETB) J9.7(RESETB)
N25448508: J8.9(UNUSED) J9.9(UNUSED) R56.2
N25448578: J7.8(OUTEN_0) R64.1
N25448791: J8.13(12V) J8.14(12V) J9.13(12V) J9.14(12V) R62.2
N25448863: J7.9(OUTEN_1) R65.1
N25449050: C46.1 R59.1
N25456892: JP4.2 R70.2 U7.5(~{SHDN})
N25459082: D2.1(CATHODE) Q4.3(D)
N25459106: D1.1(CATHODE) Q3.3(D)
N25460507: D5.2(ANODE) Q5.3(D)
N25460530: D5.1(CATHODE) R63.1
N25473428: Q7.1(G) R82.2 R83.1
N25490068: JP5.2 R81.2 U8.5(~{SHDN})
N25553671: C45.1 R58.1
N25690332: D2.2(ANODE) R47.2
N25690333: D1.2(ANODE) R46.2

Not connected (* = marked no-connect by the designer): J7 7(GPIO_1); JP4 3; JP5 3; SW1 4 5 6; SW2 4 5 6; U1 27(GL) 35(GL); U2 29(NC) 32(NC) 36(NC) 39(NC); U3 27(GL) 35(GL); U7 4(NC)*; U8 4(NC)*

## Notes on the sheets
sheet 1
- 7V-14V
- 16V
- 16V
- 1.0V/30A
- 1210
- 1210
- 1210
- 1210
- 1210
- 1210
- 1.0V/30A
- 1210
- 1210
- 1210
- 1210
- 1210
- 1210
- NOTE: UNLESS OTHERWISE SPECIFIED
- 1.  ALL RESISTORS ARE IN OHMS, 0603.
       ALL CAPACITORS ARE IN MICROFARADS, 0603.
- 2.  INSTALL SHUNTS AS SHOWN.
- AND DIGITAL POWER SYSTEM MANAGEMENT
sheet 2
- GPIO1B
- GPIO0B
- RUN1
- RUN0
- ON
- ON
- TO DC1613A
- OFF
- OFF
- ALERTB
- 1206
- C
- GPIO0-GPIO1
- NC
- C
- NC
- RUN0-RUN1
- VOUT0
- INT / EXT PULSE
- DrMOS
- VDR
- INT
- EXT
- 70Hz, 3% Duty Cycle
- ON
- IOUT
  TST
- OFF
- 1%
- 0805
- LOAD
- STEP
- VOUT1
- PULSE
- GENERATOR
- ON
- OFF
